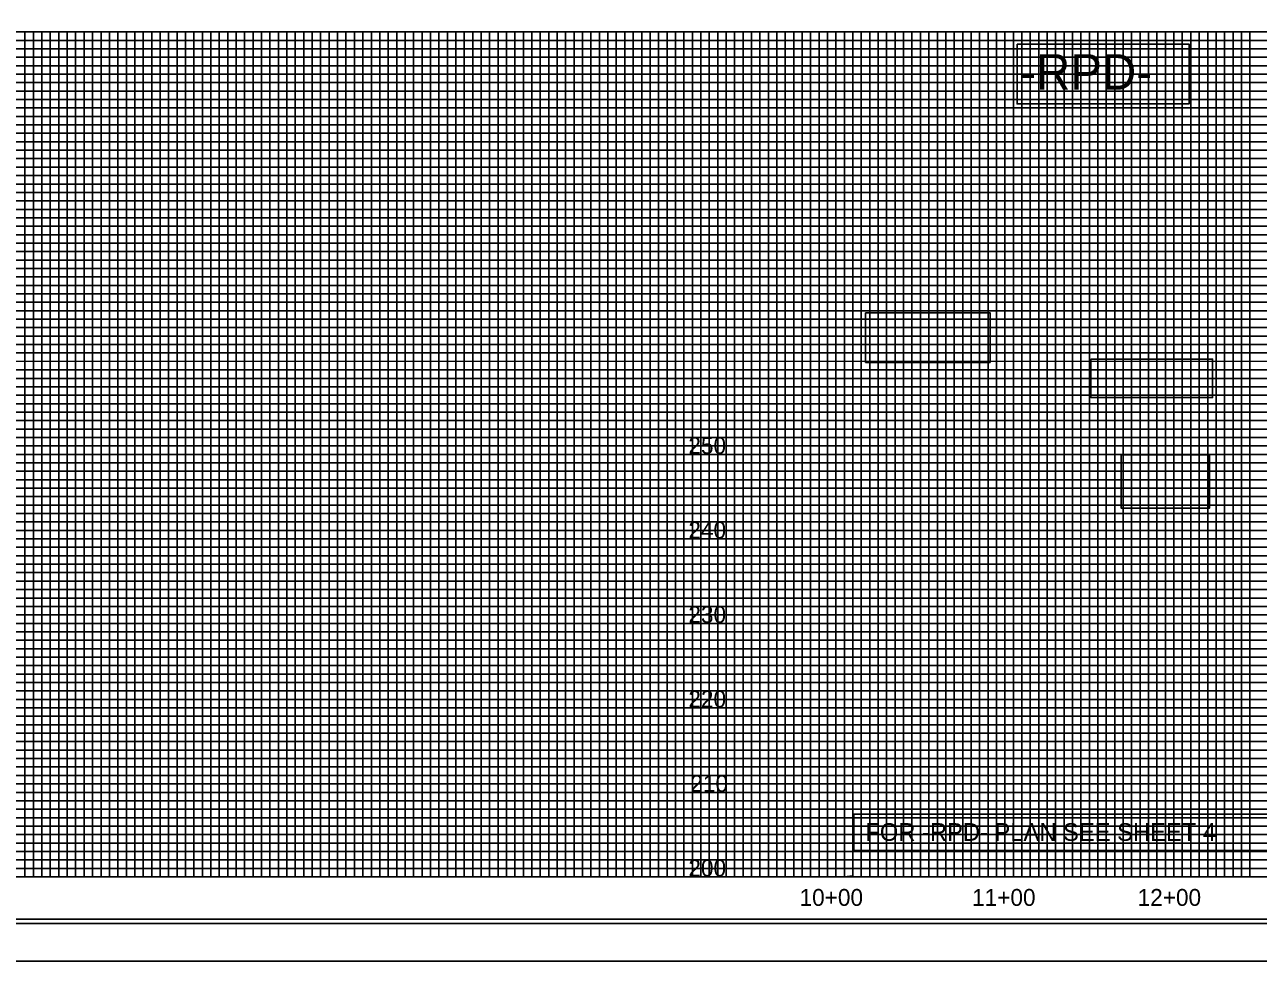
# Model space of a CAD drawing. Extents: x 1810963 to 1812960, y 722070 to 723170.
# Drawn here: x 1811500 to 1812230, y 722070 to 722624 of the extents above; entities that cross this region are included whole.
import ezdxf

# ---------------------------------------------------------------- set-up
doc = ezdxf.new("R2010")
doc.units = 0
for name, color, linetype in [('Exist Horizontal Alignment Tick Label', 7, 'Continuous'), ('Old_Level_11', 7, 'Continuous'), ('Old_Level_2', 7, 'Continuous'), ('Prop Conc 2ft 6in Curb and Gutter', 7, 'Continuous'), ('Prop RDY Traffic Signal CELL', 7, 'Continuous'), ('Prop Shade Heavy', 7, 'Continuous'), ('Prop Shade Light', 7, 'Continuous'), ('Sheet Block Title CELL', 7, 'Continuous'), ('Sheet Layout Profile Border Port 2', 7, 'Continuous'), ('Sheet North Arrow CELL', 7, 'Continuous'), ('Sheet Symbology CELL', 7, 'Continuous'), ('Sheet Title CELL', 7, 'Continuous')]:
    doc.layers.add(name, color=color, linetype=linetype)

msp = doc.modelspace()

# ---------------------------------------------------------------- linework, layer by layer
at = {"layer": 'Old_Level_11'}
msp.add_lwpolyline([(1810976.46, 722092.33), (1812642.96, 722092.33), (1812642.96, 723147.43), (1810976.46, 723147.43)], close=True, dxfattribs=at)
at = {"layer": 'Old_Level_2'}
for p, q in [((1811930.46, 722594.88), (1811880.46, 722594.88)), ((1811930.46, 722569.88), (1811880.46, 722569.88)), ((1811930.46, 722544.88), (1811880.46, 722544.88)), ((1811930.46, 722519.88), (1811880.46, 722519.88)), ((1811930.46, 722494.88), (1811880.46, 722494.88)), ((1811930.46, 722469.88), (1811880.46, 722469.88)), ((1811930.46, 722444.88), (1811880.46, 722444.88)), ((1811930.46, 722419.88), (1811880.46, 722419.88)), ((1811930.46, 722394.88), (1811880.46, 722394.88)), ((1811930.46, 722369.88), (1811880.46, 722369.88)), ((1811930.46, 722344.88), (1811880.46, 722344.88)), ((1811930.46, 722319.88), (1811880.46, 722319.88)), ((1811930.46, 722294.88), (1811880.46, 722294.88)), ((1811930.46, 722269.88), (1811880.46, 722269.88)), ((1811930.46, 722244.88), (1811880.46, 722244.88)), ((1811930.46, 722219.88), (1811880.46, 722219.88)), ((1811930.46, 722194.88), (1811880.46, 722194.88)), ((1811930.46, 722169.88), (1811880.46, 722169.88)), ((1811930.46, 722144.88), (1811880.46, 722144.88))]:
    msp.add_line(p, q, dxfattribs=at)
for points in [[(1811880.46, 722619.88), (1811930.46, 722619.88), (1811930.46, 722119.88), (1811880.46, 722119.88)], [(1812087.65, 722612.66), (1812189.44, 722612.66), (1812189.44, 722577.28), (1812087.65, 722577.28)], [(1811998, 722453.74), (1812071.69, 722453.74), (1812071.69, 722424.3), (1811998, 722424.3)], [(1812131.4, 722426.3), (1812203.33, 722426.3), (1812203.33, 722403.49), (1812131.4, 722403.49)], [(1812149.22, 722369.66), (1812201.58, 722369.66), (1812201.58, 722338.07), (1812149.22, 722338.07)], [(1811991.02, 722156.96), (1812256.15, 722156.96), (1812256.15, 722135.44), (1811991.02, 722135.44)]]:
    msp.add_lwpolyline(points, close=True, dxfattribs=at)
at = {"layer": 'Prop Conc 2ft 6in Curb and Gutter'}
for p, q in [((1811130.46, 722619.88), (1812630.35, 722619.88)), ((1811530.46, 722619.88), (1811530.46, 722119.88)), ((1811580.46, 722619.88), (1811580.46, 722119.88)), ((1811630.46, 722619.88), (1811630.46, 722119.88)), ((1811680.46, 722619.88), (1811680.46, 722119.88)), ((1811730.46, 722619.88), (1811730.46, 722119.88)), ((1811780.46, 722619.88), (1811780.46, 722119.88)), ((1811830.46, 722619.88), (1811830.46, 722119.88)), ((1811880.46, 722619.88), (1811880.46, 722119.88)), ((1811880.46, 722619.88), (1811880.46, 722119.88)), ((1811930.46, 722619.88), (1811930.46, 722119.88)), ((1811930.46, 722619.88), (1811930.46, 722119.88)), ((1811980.46, 722619.88), (1811980.46, 722119.88)), ((1812030.46, 722619.88), (1812030.46, 722119.88)), ((1812080.46, 722619.88), (1812080.46, 722119.88)), ((1812130.46, 722619.88), (1812130.46, 722119.88)), ((1812180.46, 722619.88), (1812180.46, 722119.88)), ((1811130.46, 722569.88), (1812630.35, 722569.88)), ((1811130.46, 722519.88), (1812630.35, 722519.88)), ((1811130.46, 722469.88), (1812630.35, 722469.88)), ((1811130.46, 722419.88), (1812630.35, 722419.88)), ((1811130.46, 722369.88), (1812630.35, 722369.88)), ((1811130.46, 722319.88), (1812630.35, 722319.88)), ((1811130.46, 722269.88), (1812630.35, 722269.88)), ((1811130.46, 722219.88), (1812630.35, 722219.88)), ((1811130.46, 722169.88), (1812630.35, 722169.88))]:
    msp.add_line(p, q, dxfattribs=at)
at = {"layer": 'Prop RDY Traffic Signal CELL'}
msp.add_line((1810963.46, 722069.88), (1812647.46, 722069.88), dxfattribs=at)
at = {"layer": 'Prop Shade Heavy'}
for p, q in [((1811630.46, 722619.88), (1811680.46, 722619.88)), ((1811730.46, 722619.88), (1811780.46, 722619.88)), ((1811830.46, 722619.88), (1811880.46, 722619.88)), ((1811880.46, 722619.88), (1811930.46, 722619.88)), ((1811930.46, 722619.88), (1811980.46, 722619.88)), ((1812030.46, 722619.88), (1812080.46, 722619.88)), ((1812139.61, 722619.88), (1812189.61, 722619.88))]:
    msp.add_line(p, q, dxfattribs=at)
for points in [[(1811480.46, 722119.88), (1811530.46, 722119.88), (1811530.46, 722619.88), (1811580.46, 722619.88), (1811580.46, 722119.88), (1811630.46, 722119.88), (1811630.46, 722619.88), (1811680.46, 722619.88), (1811680.46, 722119.88), (1811730.46, 722119.88), (1811730.46, 722619.88), (1811780.46, 722619.88), (1811780.46, 722119.88), (1811830.46, 722119.88), (1811830.46, 722619.88), (1811880.46, 722619.88), (1811880.46, 722119.88), (1811930.46, 722119.88), (1811930.46, 722619.88), (1811980.46, 722619.88), (1811980.46, 722119.88), (1812030.46, 722119.88), (1812030.46, 722619.88), (1812080.46, 722619.88), (1812080.46, 722119.88), (1812130.46, 722119.88), (1812130.46, 722619.88), (1812180.46, 722619.88), (1812180.46, 722119.88), (1812230.46, 722119.88)], [(1812630.46, 722569.88), (1811130.46, 722569.88)], [(1812630.46, 722519.88), (1811130.46, 722519.88), (1811130.46, 722469.88), (1812630.46, 722469.88)], [(1812630.46, 722419.88), (1811130.46, 722419.88), (1811130.46, 722369.88), (1812630.46, 722369.88)], [(1812630.46, 722319.88), (1811130.46, 722319.88), (1811130.46, 722269.88), (1812630.46, 722269.88)], [(1812630.46, 722219.88), (1811130.46, 722219.88), (1811130.46, 722219.88), (1811130.46, 722169.88), (1812630.46, 722169.88)], [(1812630.46, 722119.88), (1811130.46, 722119.88)]]:
    msp.add_lwpolyline(points, dxfattribs=at)
at = {"layer": 'Prop Shade Light'}
for points in [[(1811455.46, 722619.88), (1811505.46, 722619.88), (1811505.46, 722119.88), (1811555.46, 722119.88), (1811555.46, 722619.88), (1811605.46, 722619.88), (1811605.46, 722119.88), (1811655.46, 722119.88), (1811655.46, 722619.88), (1811705.46, 722619.88), (1811705.46, 722119.88), (1811755.46, 722119.88), (1811755.46, 722119.88), (1811755.46, 722619.88), (1811805.46, 722619.88), (1811805.46, 722119.88), (1811855.46, 722119.88), (1811855.46, 722619.88), (1811905.46, 722619.88), (1811905.46, 722119.88), (1811955.46, 722119.88), (1811955.46, 722619.88), (1812005.46, 722619.88), (1812005.46, 722119.88), (1812055.46, 722119.88), (1812055.46, 722619.88), (1812105.46, 722619.88), (1812105.46, 722119.88), (1812155.46, 722119.88), (1812155.46, 722619.88), (1812205.46, 722619.88), (1812205.46, 722119.88), (1812255.46, 722119.88)], [(1811130.46, 722594.88), (1812630.46, 722594.88)], [(1812630.46, 722544.88), (1811130.46, 722544.88), (1811130.46, 722494.88), (1812630.46, 722494.88)], [(1812630.46, 722444.88), (1811130.46, 722444.88), (1811130.46, 722394.88), (1812630.46, 722394.88)], [(1812630.46, 722344.88), (1811130.46, 722344.88), (1811130.46, 722294.88), (1812630.46, 722294.88)], [(1812630.46, 722244.88), (1811130.46, 722244.88), (1811130.46, 722194.88), (1812630.46, 722194.88)], [(1812630.46, 722144.88), (1811130.46, 722144.88)]]:
    msp.add_lwpolyline(points, dxfattribs=at)
at = {"layer": 'Sheet Layout Profile Border Port 2'}
msp.add_lwpolyline([(1811180.46, 722619.88), (1812580.46, 722619.88), (1812580.46, 722119.88), (1811180.46, 722119.88)], close=True, dxfattribs=at)
at = {"layer": 'Sheet North Arrow CELL'}
msp.add_lwpolyline([(1810963.46, 722069.88), (1812647.46, 722069.88), (1812647.46, 723169.88), (1810963.46, 723169.88)], close=True, dxfattribs=at)
at = {"layer": 'Sheet Symbology CELL'}
for p, q in [((1811130.46, 722619.88), (1812630.46, 722619.88)), ((1812630.46, 722119.88), (1811130.46, 722119.88)), ((1811130.46, 722094.88), (1812630.46, 722094.88))]:
    msp.add_line(p, q, dxfattribs=at)
msp.add_lwpolyline([(1812630.46, 723144.88), (1811130.46, 723144.88), (1811130.46, 722094.88), (1812630.46, 722094.88)], close=True, dxfattribs=at)
at = {"layer": 'Sheet Title CELL'}
for p, q in [((1811180.46, 722614.88), (1812580.46, 722614.88)), ((1812580.46, 722609.88), (1811180.46, 722609.88)), ((1811180.46, 722604.88), (1812580.46, 722604.88)), ((1812580.46, 722599.88), (1811180.46, 722599.88)), ((1811180.46, 722589.88), (1812580.46, 722589.88)), ((1812580.46, 722584.88), (1811180.46, 722584.88)), ((1811180.46, 722579.88), (1812580.46, 722579.88)), ((1812580.46, 722574.88), (1811180.46, 722574.88)), ((1811180.46, 722564.88), (1812580.46, 722564.88)), ((1812580.46, 722559.88), (1811180.46, 722559.88)), ((1811180.46, 722554.88), (1812580.46, 722554.88)), ((1812580.46, 722549.88), (1811180.46, 722549.88)), ((1811180.46, 722539.88), (1812580.46, 722539.88)), ((1812580.46, 722534.88), (1811180.46, 722534.88)), ((1811180.46, 722529.88), (1812580.46, 722529.88)), ((1812580.46, 722524.88), (1811180.46, 722524.88)), ((1811180.46, 722514.88), (1812580.46, 722514.88)), ((1812580.46, 722509.88), (1811180.46, 722509.88)), ((1811180.46, 722504.88), (1812580.46, 722504.88)), ((1812580.46, 722499.88), (1811180.46, 722499.88)), ((1811180.46, 722489.88), (1812580.46, 722489.88)), ((1812580.46, 722484.88), (1811180.46, 722484.88)), ((1811180.46, 722479.88), (1812580.46, 722479.88)), ((1812580.46, 722474.88), (1811180.46, 722474.88)), ((1811180.46, 722464.88), (1812580.46, 722464.88)), ((1812580.46, 722459.88), (1811180.46, 722459.88)), ((1811180.46, 722454.88), (1812580.46, 722454.88)), ((1812580.46, 722449.88), (1811180.46, 722449.88)), ((1811180.46, 722439.88), (1812580.46, 722439.88)), ((1812580.46, 722434.88), (1811180.46, 722434.88)), ((1811180.46, 722429.88), (1812580.46, 722429.88)), ((1812580.46, 722424.88), (1811180.46, 722425.03)), ((1811180.46, 722414.88), (1812580.46, 722414.88)), ((1812580.46, 722409.88), (1811180.46, 722409.88)), ((1811180.46, 722404.88), (1812580.46, 722404.88)), ((1812580.46, 722399.88), (1811180.46, 722399.88)), ((1811180.46, 722389.88), (1812580.46, 722389.88)), ((1812580.46, 722384.88), (1811180.46, 722384.88)), ((1811180.46, 722379.88), (1812580.46, 722379.88)), ((1812580.46, 722374.88), (1811180.46, 722374.88)), ((1811180.46, 722364.88), (1812580.46, 722364.88)), ((1812580.46, 722359.88), (1811180.46, 722359.88)), ((1811180.46, 722354.88), (1812580.46, 722354.88)), ((1812580.46, 722349.88), (1811180.46, 722349.88)), ((1811180.46, 722339.88), (1812580.46, 722339.88)), ((1812580.46, 722334.88), (1811180.46, 722334.88)), ((1811180.46, 722329.88), (1812580.46, 722329.88)), ((1812580.46, 722324.88), (1811180.46, 722324.88)), ((1811180.46, 722314.88), (1812580.46, 722314.88)), ((1812580.46, 722309.88), (1811180.46, 722309.88)), ((1811180.46, 722304.88), (1812580.46, 722304.88)), ((1812580.46, 722299.88), (1811180.46, 722299.88)), ((1811180.46, 722289.88), (1812580.46, 722289.88)), ((1812580.46, 722284.88), (1811180.46, 722284.88)), ((1811180.46, 722279.88), (1812580.46, 722279.88)), ((1812580.46, 722274.88), (1811180.46, 722274.88)), ((1811180.46, 722264.88), (1812580.46, 722264.88)), ((1812580.46, 722259.88), (1811180.46, 722259.88)), ((1811180.46, 722254.88), (1812580.46, 722254.88)), ((1812580.46, 722249.88), (1811180.46, 722249.88)), ((1811180.46, 722239.88), (1812580.46, 722239.88)), ((1812580.46, 722234.88), (1811180.46, 722234.88)), ((1811180.46, 722229.88), (1812580.46, 722229.88)), ((1812580.46, 722224.88), (1811180.46, 722224.88)), ((1811180.46, 722214.88), (1812580.46, 722214.88)), ((1812580.46, 722209.88), (1811180.46, 722209.88)), ((1811180.46, 722204.88), (1812580.46, 722204.88)), ((1812580.46, 722199.88), (1811180.46, 722199.88)), ((1811180.46, 722189.88), (1812580.46, 722189.88)), ((1812580.46, 722184.88), (1811180.46, 722184.88)), ((1811180.46, 722179.88), (1812580.46, 722179.88)), ((1812580.46, 722174.88), (1811180.46, 722174.88)), ((1811180.46, 722164.88), (1812580.46, 722164.88)), ((1812580.46, 722159.88), (1811180.46, 722159.88)), ((1811180.46, 722154.88), (1812580.46, 722154.88)), ((1812580.46, 722149.88), (1811180.46, 722149.88)), ((1811180.46, 722139.88), (1812580.46, 722139.88)), ((1812580.46, 722134.88), (1811180.46, 722134.88)), ((1811180.46, 722129.88), (1812580.46, 722129.88)), ((1811180.46, 722124.88), (1812580.46, 722124.88))]:
    msp.add_line(p, q, dxfattribs=at)
for points in [[(1811495.46, 722119.88), (1811500.46, 722119.88), (1811500.46, 722619.88), (1811510.46, 722619.88), (1811510.46, 722119.88), (1811515.46, 722119.88), (1811515.46, 722619.88), (1811520.46, 722619.88), (1811520.46, 722119.88), (1811525.46, 722119.88), (1811525.46, 722619.88), (1811535.46, 722619.88), (1811535.46, 722119.88), (1811540.46, 722119.88), (1811540.46, 722619.88), (1811545.46, 722619.88), (1811545.46, 722119.88), (1811550.46, 722119.88), (1811550.46, 722619.88), (1811560.46, 722619.88), (1811560.46, 722119.88), (1811565.46, 722119.88), (1811565.46, 722619.88), (1811570.46, 722619.88), (1811570.46, 722119.88), (1811575.46, 722119.88), (1811575.46, 722619.88), (1811585.46, 722619.88), (1811585.46, 722119.88), (1811590.46, 722119.88), (1811590.46, 722619.88), (1811595.46, 722619.88), (1811595.46, 722119.88), (1811600.46, 722119.88), (1811600.46, 722619.88), (1811610.46, 722619.88), (1811610.46, 722119.88), (1811615.46, 722119.88), (1811615.46, 722619.88), (1811620.46, 722619.88), (1811620.46, 722119.88), (1811625.46, 722119.88), (1811625.46, 722619.88), (1811635.46, 722619.88), (1811635.46, 722119.88), (1811640.46, 722119.88), (1811640.46, 722619.88), (1811645.46, 722619.88), (1811645.46, 722119.88), (1811650.46, 722119.88), (1811650.46, 722619.88), (1811660.46, 722619.88), (1811660.46, 722119.88), (1811665.46, 722119.88), (1811665.46, 722619.88), (1811670.46, 722619.88), (1811670.46, 722119.88), (1811675.46, 722119.88), (1811675.46, 722619.88), (1811685.46, 722619.88), (1811685.46, 722119.88), (1811690.46, 722119.88), (1811690.46, 722619.88), (1811695.46, 722619.88), (1811695.46, 722119.88), (1811700.46, 722119.88), (1811700.46, 722619.88), (1811710.46, 722619.88)], [(1811710.46, 722619.88), (1811710.46, 722119.88), (1811715.46, 722119.88), (1811715.46, 722619.88), (1811720.46, 722619.88), (1811720.46, 722119.88), (1811725.46, 722119.88), (1811725.46, 722619.88), (1811735.46, 722619.88), (1811735.46, 722119.88), (1811740.46, 722119.88), (1811740.46, 722619.88), (1811745.46, 722619.88), (1811745.46, 722119.88), (1811750.46, 722119.88), (1811750.46, 722619.88), (1811760.46, 722619.88), (1811760.46, 722119.88), (1811765.46, 722119.88), (1811765.46, 722619.88), (1811770.46, 722619.88), (1811770.46, 722119.88), (1811775.46, 722119.88), (1811775.46, 722619.88), (1811785.46, 722619.88), (1811785.46, 722119.88), (1811790.46, 722119.88), (1811790.46, 722619.88), (1811795.46, 722619.88), (1811795.46, 722119.88), (1811800.46, 722119.88), (1811800.46, 722619.88), (1811810.46, 722619.88), (1811810.46, 722119.88), (1811815.46, 722119.88), (1811815.46, 722619.88), (1811820.46, 722619.88), (1811820.46, 722119.88), (1811825.46, 722119.88), (1811825.46, 722619.88), (1811835.46, 722619.88), (1811835.46, 722119.88), (1811835.46, 722119.88), (1811840.46, 722119.88), (1811840.46, 722619.88), (1811845.46, 722619.88), (1811845.46, 722119.88), (1811850.46, 722119.88), (1811850.46, 722619.88), (1811860.46, 722619.88), (1811860.46, 722119.88), (1811865.46, 722119.88), (1811865.46, 722619.88), (1811870.46, 722619.88), (1811870.46, 722119.88), (1811875.46, 722119.88), (1811875.46, 722619.88), (1811885.46, 722619.88), (1811885.46, 722119.88), (1811890.46, 722119.88), (1811890.46, 722619.88), (1811895.46, 722619.88), (1811895.46, 722119.88), (1811900.46, 722119.88), (1811900.46, 722619.88), (1811910.46, 722619.88), (1811910.46, 722119.88), (1811915.46, 722119.88), (1811915.46, 722619.88), (1811920.46, 722619.88), (1811920.46, 722119.88), (1811925.46, 722119.88), (1811925.46, 722619.88), (1811935.46, 722619.88), (1811935.46, 722119.88), (1811940.46, 722119.88), (1811940.46, 722619.88), (1811945.46, 722619.88), (1811945.46, 722119.88), (1811950.46, 722119.88), (1811950.46, 722619.88), (1811960.46, 722619.88), (1811960.46, 722119.88), (1811965.46, 722119.88), (1811965.46, 722619.88), (1811970.46, 722619.88), (1811970.46, 722119.88), (1811975.46, 722119.88), (1811975.46, 722619.88), (1811985.46, 722619.88), (1811985.46, 722119.88), (1811990.16, 722120.43), (1811990.46, 722119.88), (1811990.46, 722619.88), (1811995.46, 722619.88), (1811995.46, 722119.88), (1812000.46, 722119.88), (1812000.46, 722619.88), (1812010.46, 722619.88), (1812010.46, 722119.88), (1812015.46, 722119.88)], [(1812015.46, 722119.88), (1812015.46, 722619.88), (1812020.46, 722619.88), (1812020.46, 722119.88), (1812025.46, 722119.88), (1812025.46, 722619.88), (1812035.46, 722619.88), (1812035.46, 722119.88), (1812040.46, 722119.88), (1812040.46, 722619.88), (1812045.46, 722619.88), (1812045.46, 722119.88), (1812050.46, 722119.88), (1812050.46, 722619.88), (1812060.46, 722619.88), (1812060.46, 722119.88), (1812065.46, 722119.88), (1812065.46, 722619.88), (1812070.46, 722619.88), (1812070.46, 722119.88), (1812075.46, 722119.88), (1812075.46, 722619.88), (1812085.46, 722619.88), (1812085.46, 722119.88), (1812090.46, 722119.88), (1812090.46, 722619.88), (1812095.46, 722619.88), (1812095.46, 722119.88), (1812100.46, 722119.88), (1812100.46, 722619.88), (1812110.46, 722619.88), (1812110.46, 722119.88), (1812115.46, 722119.88), (1812115.46, 722619.88), (1812120.46, 722619.88), (1812120.46, 722119.88), (1812125.46, 722119.88), (1812125.46, 722619.88), (1812135.46, 722619.88), (1812135.46, 722119.88), (1812140.46, 722119.88), (1812140.46, 722619.88), (1812145.46, 722619.88), (1812145.46, 722119.88), (1812150.46, 722119.88), (1812150.46, 722619.88), (1812160.46, 722619.88), (1812160.46, 722119.88), (1812165.46, 722119.88), (1812165.46, 722619.88), (1812170.46, 722619.88), (1812170.46, 722119.88), (1812175.46, 722119.88), (1812175.46, 722619.88), (1812185.46, 722619.88), (1812185.46, 722119.88), (1812190.46, 722119.88), (1812190.46, 722619.88), (1812195.46, 722619.88), (1812195.46, 722119.88), (1812200.46, 722119.88), (1812200.46, 722619.88), (1812210.46, 722619.88), (1812210.46, 722119.88), (1812215.46, 722119.88), (1812215.46, 722619.88), (1812220.46, 722619.88), (1812220.46, 722119.88), (1812225.46, 722119.88), (1812225.46, 722619.88), (1812235.46, 722619.88)]]:
    msp.add_lwpolyline(points, dxfattribs=at)

# ---------------------------------------------------------------- texts
at = {"layer": 'Exist Horizontal Alignment Tick Label'}
for s, height, p in [('-RPD-', 21, (1812089.53, 722585.71)), ('FOR -RPD- PLAN SEE SHEET 4', 10.5, (1811997.85, 722141.15))]:
    msp.add_text(s, height=height, rotation=360, dxfattribs=at).set_placement(p)
at = {"layer": 'Old_Level_2'}
for s, p in [('250', (1811893.1, 722370.13)), ('240', (1811893.1, 722320.13)), ('230', (1811893.1, 722270.13)), ('220', (1811893.1, 722220.13)), ('210', (1811894.29, 722170.13)), ('200', (1811893.1, 722120.13))]:
    msp.add_text(s, height=10, dxfattribs=at).set_placement(p)
at = {"layer": 'Sheet Block Title CELL'}
for s, p in [('10+00', (1811958.92, 722102.7)), ('11+00', (1812061.03, 722102.7)), ('12+00', (1812159.01, 722102.7))]:
    msp.add_text(s, height=10, dxfattribs=at).set_placement(p)

doc.saveas('drawing.dxf')
